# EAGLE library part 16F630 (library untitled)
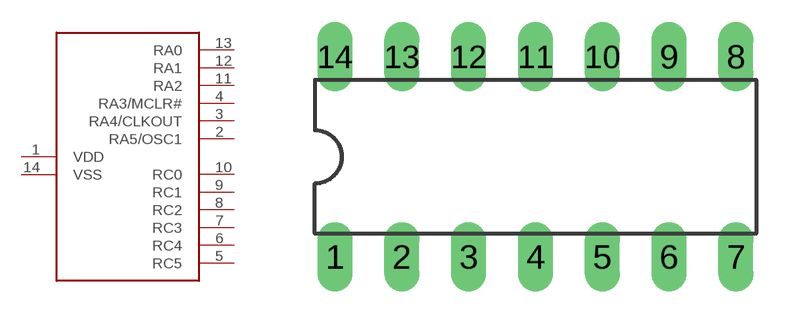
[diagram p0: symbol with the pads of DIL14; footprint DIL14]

Designator prefix -

## 16F630  [DIL14]
1  VDD  sup
2  RA5/OSC1
3  RA4/CLKOUT
4  RA3/MCLR#  in
5  RC5
6  RC4
7  RC3
8  RC2
9  RC1
10  RC0
11  RA2
12  RA1
13  RA0
14  VSS  sup

## Footprint DIL14 (pad centres in mm)
Dual In Line Package
drill 0.813 long: 1 -7.62,-3.81; 2 -5.08,-3.81; 3 -2.54,-3.81; 4 0,-3.81; 5 2.54,-3.81; 6 5.08,-3.81; 7 7.62,-3.81; 8 7.62,3.81; 9 5.08,3.81; 10 2.54,3.81; 11 0,3.81; 12 -2.54,3.81; 13 -5.08,3.81; 14 -7.62,3.81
